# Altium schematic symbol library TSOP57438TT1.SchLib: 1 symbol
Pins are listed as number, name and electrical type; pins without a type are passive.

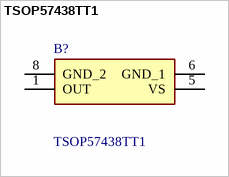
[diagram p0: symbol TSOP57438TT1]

## TSOP57438TT1
designator B?
VISHAY - TSOP57438TT1 - IR RECEIVER, BELOBOG AGC4, 38KHZ; Geometry.Height: 0.8mm
footprint TSOP57438TT1
pins: 1 OUT, 5 VS, 6 GND_1, 8 GND_2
